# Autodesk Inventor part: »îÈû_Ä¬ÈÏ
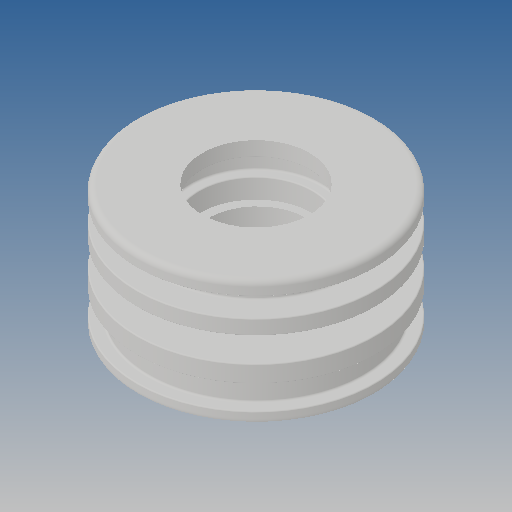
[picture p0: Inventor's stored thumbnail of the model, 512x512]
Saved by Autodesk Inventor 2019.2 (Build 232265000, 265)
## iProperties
Created: 2011-12
Part Number: »îÈû_Ä¬ÈÏ
Material: Ogólny
Document SubType Name: Modeling
Designer: CADENGINEERING4
Density: 1 g/cm^3
Appearance: Domyślna
Author: CADENGINEERING4
Revision Number: ÈÎºÎ
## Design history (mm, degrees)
feature "NONE"
node "Bryła1"
